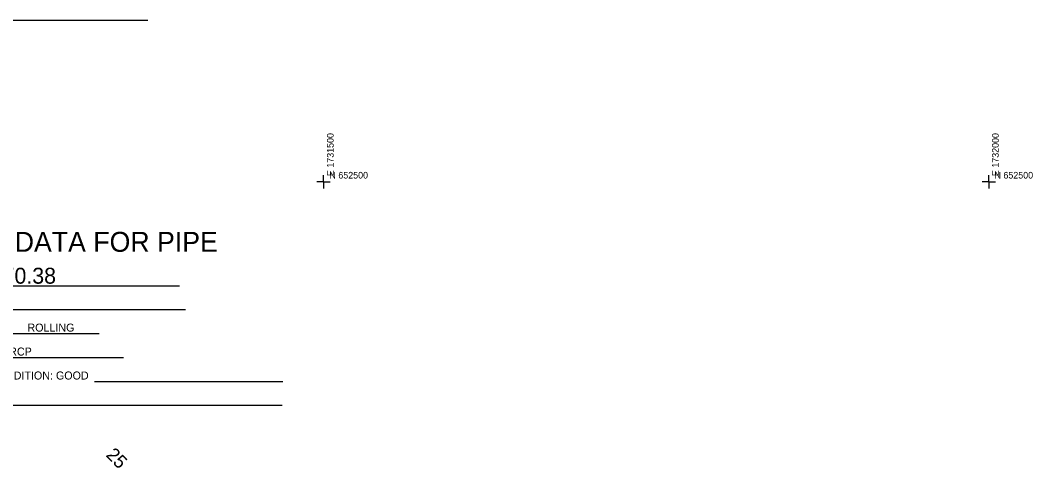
# Model space of a CAD drawing. Extents: x 1729869 to 1735532, y 648588 to 653771.
# Drawn here: x 1731272 to 1732033, y 652285 to 652622 of the extents above; entities that cross this region are included whole.
import ezdxf

# ---------------------------------------------------------------- set-up
doc = ezdxf.new("R2010")
doc.units = 0
for name, color, linetype in [('SURVEY - CENTERLINE - Preliminary Text', 7, 'Continuous'), ('SURVEY - CONTROL - Grid', 7, 'Continuous'), ('SURVEY - CONTROL - Grid Text', 7, 'Continuous'), ('SURVEY - DRAINAGE - Area Shapes Text', 7, 'Continuous')]:
    doc.layers.add(name, color=color, linetype=linetype)

msp = doc.modelspace()

# ---------------------------------------------------------------- linework, layer by layer
at = {"layer": 'SURVEY - CONTROL - Grid'}
for p, q in [((1731500, 652500), (1731500, 652505)), ((1732000, 652500), (1732000, 652505)), ((1731500, 652500), (1731495, 652500)), ((1731500, 652500), (1731505, 652500)), ((1731500, 652500), (1731500, 652495)), ((1732000, 652500), (1731995, 652500)), ((1732000, 652500), (1732005, 652500)), ((1732000, 652500), (1732000, 652495))]:
    msp.add_line(p, q, dxfattribs=at)
at = {"layer": 'SURVEY - DRAINAGE - Area Shapes Text'}
for p, q in [((1731103.48, 652621.59), (1731367.83, 652621.59)), ((1731241.42, 652421.89), (1731391.72, 652421.89)), ((1731260.27, 652403.89), (1731396.22, 652403.89)), ((1731236.77, 652385.89), (1731331.17, 652385.89)), ((1731263.17, 652367.89), (1731349.42, 652367.89)), ((1731327.77, 652349.89), (1731469.37, 652349.89)), ((1731204.42, 652331.89), (1731468.77, 652331.89))]:
    msp.add_line(p, q, dxfattribs=at)

# ---------------------------------------------------------------- texts
at = {"layer": 'SURVEY - CENTERLINE - Preliminary Text'}
msp.add_text('25', height=10, rotation=314.45532, dxfattribs=at).set_placement((1731335.74, 652294))
at = {"layer": 'SURVEY - CONTROL - Grid Text'}
for s, p in [(' E 1731500 ', (1731507.5, 652502.5)), (' E 1732000 ', (1732007.5, 652502.5))]:
    msp.add_text(s, height=5, rotation=90, dxfattribs=at).set_placement(p)
for p in [(1731502.5, 652502.5), (1732002.5, 652502.5)]:
    msp.add_text(' N 652500 ', height=5, dxfattribs=at).set_placement(p)
at = {"layer": 'SURVEY - DRAINAGE - Area Shapes Text'}
for s, height, p in [('DRAINAGE DATA FOR PIPE', 15, (1731157.42, 652447.39)), ('STATION 22+70.38            ', 12, (1731157.42, 652423.39)), ('DRAINAGE AREA 1.467 AC        ROLLING', 6.0198, (1731157.42, 652387.35)), ('PRESENT STRUCTURE: 24"RCP                      ', 6.0198, (1731157.42, 652369.33)), ('EXISTING STRUCTURE CONDITION: GOOD                      ', 6.0198, (1731157.42, 652351.31))]:
    msp.add_text(s, height=height, dxfattribs=at).set_placement(p)

doc.saveas('drawing.dxf')
